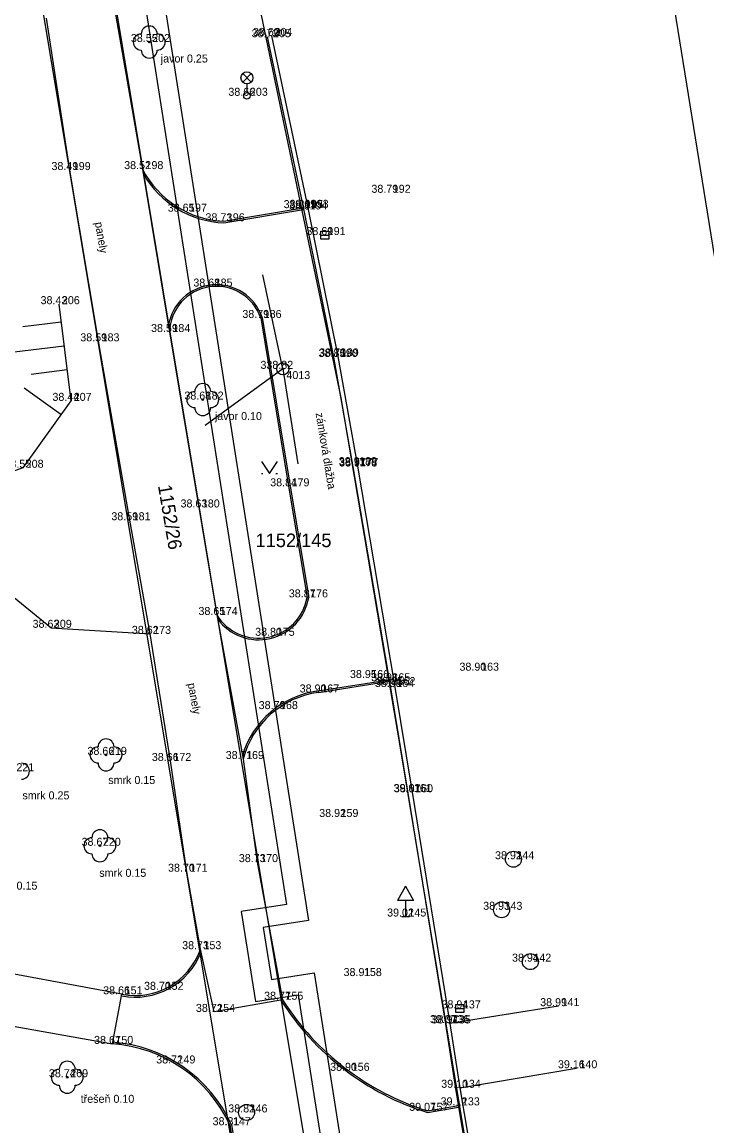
# Model space of a CAD drawing. Extents: x -609709 to -609357, y -1051535 to -1051131.
# Drawn here: x -609518.29 to -609496.91, y -1051297.25 to -1051262.77 of the extents above; entities that cross this region are included whole.
import ezdxf

# ---------------------------------------------------------------- set-up
doc = ezdxf.new("R2010")
doc.units = 0
for name, color, linetype in [('Vrstva 1', 7, 'Continuous'), ('Vrstva 10', 7, 'Continuous'), ('Vrstva 18', 7, 'Continuous'), ('Vrstva 19', 7, 'Continuous'), ('Vrstva 2', 7, 'Continuous'), ('Vrstva 3', 7, 'Continuous'), ('Vrstva 4', 7, 'Continuous'), ('Vrstva 5', 7, 'Continuous'), ('Vrstva 6', 7, 'Continuous'), ('Vrstva 7', 7, 'Continuous'), ('Vrstva 8', 7, 'Continuous')]:
    doc.layers.add(name, color=color, linetype=linetype)

msp = doc.modelspace()

# ---------------------------------------------------------------- linework, layer by layer
at = {"layer": 'Vrstva 1'}
for p, q in [((-609514.32, -1051263.39), (-609514.32, -1051263.39)), ((-609510.55, -1051263.24), (-609510.55, -1051263.24)), ((-609510.5, -1051263.2), (-609510.5, -1051263.2)), ((-609511.27, -1051265.07), (-609511.27, -1051265.07)), ((-609516.8, -1051267.39), (-609516.8, -1051267.39)), ((-609514.53, -1051267.36), (-609514.53, -1051267.36)), ((-609506.81, -1051268.1), (-609506.81, -1051268.1)), ((-609509.54, -1051268.58), (-609509.54, -1051268.58)), ((-609509.41, -1051268.62), (-609509.41, -1051268.62)), ((-609509.37, -1051268.57), (-609509.37, -1051268.57)), ((-609513.17, -1051268.69), (-609513.17, -1051268.69)), ((-609511.99, -1051268.99), (-609511.99, -1051268.99)), ((-609508.84, -1051269.42), (-609508.84, -1051269.42)), ((-609512.37, -1051271.03), (-609512.37, -1051271.03)), ((-609517.14, -1051271.58), (-609517.14, -1051271.58)), ((-609510.84, -1051272.01), (-609510.84, -1051272.01)), ((-609513.69, -1051272.45), (-609513.69, -1051272.45)), ((-609515.9, -1051272.74), (-609515.9, -1051272.74)), ((-609508.46, -1051273.23), (-609508.46, -1051273.23)), ((-609508.43, -1051273.21), (-609508.43, -1051273.21)), ((-609510.15, -1051273.6), (-609510.15, -1051273.6)), ((-609516.77, -1051274.6), (-609516.77, -1051274.6)), ((-609512.65, -1051274.56), (-609512.65, -1051274.56)), ((-609518.27, -1051276.69), (-609518.27, -1051276.69)), ((-609507.86, -1051276.61), (-609507.86, -1051276.61)), ((-609507.85, -1051276.65), (-609507.85, -1051276.65)), ((-609507.82, -1051276.64), (-609507.82, -1051276.64)), ((-609509.97, -1051277.27), (-609509.97, -1051277.27)), ((-609512.77, -1051277.93), (-609512.77, -1051277.93)), ((-609514.93, -1051278.33), (-609514.93, -1051278.33)), ((-609509.39, -1051280.74), (-609509.39, -1051280.74)), ((-609512.21, -1051281.29), (-609512.21, -1051281.29)), ((-609517.39, -1051281.69), (-609517.39, -1051281.69)), ((-609514.29, -1051281.88), (-609514.29, -1051281.88)), ((-609510.43, -1051281.94), (-609510.43, -1051281.94)), ((-609504.05, -1051283.03), (-609504.05, -1051283.03)), ((-609507.48, -1051283.26), (-609507.48, -1051283.26)), ((-609506.82, -1051283.36), (-609506.82, -1051283.36)), ((-609506.66, -1051283.48), (-609506.66, -1051283.48)), ((-609509.04, -1051283.71), (-609509.04, -1051283.71)), ((-609506.7, -1051283.54), (-609506.7, -1051283.54)), ((-609510.33, -1051284.23), (-609510.33, -1051284.23)), ((-609515.67, -1051285.66), (-609515.67, -1051285.66)), ((-609513.66, -1051285.85), (-609513.66, -1051285.85)), ((-609511.39, -1051285.79), (-609511.39, -1051285.79)), ((-609506.15, -1051286.82), (-609506.15, -1051286.82)), ((-609506.11, -1051286.83), (-609506.11, -1051286.83)), ((-609508.44, -1051287.6), (-609508.44, -1051287.6)), ((-609515.86, -1051288.5), (-609515.86, -1051288.5)), ((-609510.95, -1051289.01), (-609510.95, -1051289.01)), ((-609502.95, -1051288.92), (-609502.95, -1051288.92)), ((-609513.15, -1051289.31), (-609513.15, -1051289.31)), ((-609506.32, -1051290.71), (-609506.32, -1051290.71)), ((-609503.32, -1051290.5), (-609503.32, -1051290.5)), ((-609512.72, -1051291.73), (-609512.72, -1051291.73)), ((-609502.42, -1051292.12), (-609502.42, -1051292.12)), ((-609507.71, -1051292.57), (-609507.71, -1051292.57)), ((-609515.18, -1051293.14), (-609515.18, -1051293.14)), ((-609513.9, -1051293), (-609513.9, -1051293)), ((-609510.16, -1051293.31), (-609510.16, -1051293.31)), ((-609512.29, -1051293.69), (-609512.29, -1051293.69)), ((-609504.62, -1051293.58), (-609504.62, -1051293.58)), ((-609501.54, -1051293.51), (-609501.54, -1051293.51)), ((-609504.98, -1051294.04), (-609504.98, -1051294.04)), ((-609504.93, -1051294.05), (-609504.93, -1051294.05)), ((-609515.47, -1051294.69), (-609515.47, -1051294.69)), ((-609513.53, -1051295.3), (-609513.53, -1051295.3)), ((-609508.09, -1051295.53), (-609508.09, -1051295.53)), ((-609500.98, -1051295.45), (-609500.98, -1051295.45)), ((-609516.88, -1051295.73), (-609516.88, -1051295.73)), ((-609504.62, -1051296.06), (-609504.62, -1051296.06)), ((-609511.28, -1051296.83), (-609511.28, -1051296.83)), ((-609505.63, -1051296.78), (-609505.63, -1051296.78)), ((-609504.65, -1051296.61), (-609504.65, -1051296.61)), ((-609511.8, -1051297.23), (-609511.8, -1051297.23))]:
    msp.add_line(p, q, dxfattribs=at)
at = {"layer": 'Vrstva 10'}
for p, q in [((-609517.43, -1051249.92), (-609506.51, -1051315.51)), ((-609519.54, -1051251.09), (-609508.96, -1051314.48)), ((-609511.43, -1051259.63), (-609508.34, -1051274.51)), ((-609498.31, -1051259.99), (-609492.16, -1051298.11)), ((-609508.34, -1051274.51), (-609506.48, -1051285.5)), ((-609510.82, -1051276.495), (-609510.57, -1051276.87)), ((-609510.57, -1051276.87), (-609510.32, -1051276.495)), ((-609510.82, -1051276.87), (-609510.77, -1051276.87)), ((-609510.37, -1051276.87), (-609510.32, -1051276.87)), ((-609506.48, -1051285.5), (-609502.54, -1051309.21))]:
    msp.add_line(p, q, dxfattribs=at)
at = {"layer": 'Vrstva 18'}
for points in [[(-609510.15, -1051273.6), (-609510.778, -1051270.666)], [(-609510.15, -1051273.6), (-609512.571, -1051275.372)], [(-609510.15, -1051273.6), (-609509.678, -1051276.563)]]:
    msp.add_lwpolyline(points, dxfattribs=at)
for radius in [0.188, 0.025]:
    msp.add_circle((-609510.15, -1051273.6), radius, dxfattribs=at)
at = {"layer": 'Vrstva 19'}
for points in [[(-609514.503, -1051261.893), (-609510.036, -1051290.33), (-609511.446, -1051290.552), (-609511.003, -1051293.366), (-609509.669, -1051293.157), (-609503.864, -1051330.113)], [(-609513.91, -1051261.8), (-609509.35, -1051290.83), (-609510.76, -1051291.051), (-609510.504, -1051292.681), (-609509.17, -1051292.471), (-609503.272, -1051330.02)]]:
    msp.add_lwpolyline(points, dxfattribs=at)
at = {"layer": 'Vrstva 4'}
for p, q in [((-609511.987, -1051269.04), (-609509.502, -1051268.624)), ((-609510.791, -1051271.998), (-609509.921, -1051277.262)), ((-609509.921, -1051277.262), (-609509.339, -1051280.74)), ((-609509.047, -1051283.661), (-609506.831, -1051283.311)), ((-609505.633, -1051296.831), (-609504.661, -1051296.663))]:
    msp.add_line(p, q, dxfattribs=at)
for points in [[(-609515.4, -1051262.34), (-609514.53, -1051267.36), (-609513.69, -1051272.45), (-609512.77, -1051277.93), (-609512.21, -1051281.29), (-609511.39, -1051285.79), (-609510.95, -1051289.01), (-609510.16, -1051293.31), (-609512.29, -1051293.69), (-609512.72, -1051291.73)], [(-609512.72, -1051291.73), (-609513.15, -1051289.31), (-609513.66, -1051285.85), (-609514.29, -1051281.88), (-609514.93, -1051278.33), (-609515.9, -1051272.74), (-609516.8, -1051267.39), (-609517.53, -1051262.64)], [(-609510.637, -1051263.229), (-609509.507, -1051268.598), (-609508.568, -1051273.236), (-609507.958, -1051276.664), (-609506.798, -1051283.503), (-609506.248, -1051286.853), (-609505.068, -1051294.072), (-609504.758, -1051296.082), (-609504.098, -1051300.034), (-609503.728, -1051302.044), (-609503.168, -1051305.323), (-609502.501, -1051309.562)], [(-609510.5, -1051263.2), (-609509.37, -1051268.57), (-609508.43, -1051273.21), (-609507.82, -1051276.64), (-609506.66, -1051283.48), (-609506.11, -1051286.83), (-609504.93, -1051294.05), (-609504.62, -1051296.06), (-609503.96, -1051300.01), (-609503.59, -1051302.02), (-609503.03, -1051305.3), (-609502.36, -1051309.56)], [(-609511.99, -1051268.99), (-609509.512, -1051268.575)], [(-609510.84, -1051272.01), (-609509.97, -1051277.27), (-609509.39, -1051280.74)], [(-609517.39, -1051281.69), (-609519.87, -1051279.67), (-609524.23, -1051280.8), (-609526, -1051281.87)], [(-609517.39, -1051281.69), (-609514.29, -1051281.88)], [(-609509.04, -1051283.71), (-609506.822, -1051283.36)], [(-609515.47, -1051294.69), (-609515.18, -1051293.14), (-609520.01, -1051292.24), (-609525.19, -1051291.37), (-609531.18, -1051290.39), (-609535.64, -1051290.75), (-609539.66, -1051291.12)], [(-609542.53, -1051294.7), (-609539.02, -1051292.72), (-609535.48, -1051292.43), (-609531.05, -1051292.05), (-609525.42, -1051293.02), (-609520.39, -1051293.81), (-609515.47, -1051294.69)], [(-609501.54, -1051293.51), (-609504.93, -1051294.05)], [(-609504.62, -1051296.06), (-609500.98, -1051295.45)], [(-609505.63, -1051296.78), (-609504.669, -1051296.613)], [(-609511.8, -1051297.23), (-609510.59, -1051304.41), (-609509.94, -1051308.35), (-609509.47, -1051311.16), (-609511.1, -1051315.86)], [(-609511.752, -1051297.215), (-609510.541, -1051304.402), (-609509.891, -1051308.342), (-609509.419, -1051311.164), (-609511.053, -1051315.876)]]:
    msp.add_lwpolyline(points, dxfattribs=at)
for centre, radius, start, end in [((-609511.854, -1051265.984), 3.009, 207.2139, 267.4069), ((-609511.854, -1051265.984), 3.059, 209.9249, 267.5065), ((-609512.225, -1051272.488), 1.515, 18.8847, 171.1163), ((-609512.225, -1051272.488), 1.465, 19.0457, 178.507), ((-609510.905, -1051280.478), 1.537, 211.8899, 350.1824), ((-609510.905, -1051280.478), 1.587, 216.0744, 350.4918), ((-609508.664, -1051286.502), 2.867, 97.6736, 163.2956), ((-609508.664, -1051286.502), 2.817, 97.6623, 165.3622), ((-609514.765, -1051291.013), 2.167, 258.9582, 340.682), ((-609514.765, -1051291.013), 2.217, 258.9682, 338.6471), ((-609503.145, -1051288.844), 8.366, 212.3408, 252.6968), ((-609503.145, -1051288.844), 8.316, 212.4817, 252.6138), ((-609515.776, -1051299.054), 4.375, 24.64, 85.9859), ((-609515.776, -1051299.054), 4.425, 24.5541, 85.9112)]:
    msp.add_arc(centre, radius, start, end, dxfattribs=at)
at = {"layer": 'Vrstva 5'}
for p, q in [((-609511.402, -1051264.64), (-609511.138, -1051264.375)), ((-609511.402, -1051264.375), (-609511.138, -1051264.64)), ((-609511.27, -1051264.695), (-609511.27, -1051264.97)), ((-609508.965, -1051269.42), (-609508.715, -1051269.42)), ((-609506.32, -1051289.76), (-609506.57, -1051290.21)), ((-609506.32, -1051289.76), (-609506.07, -1051290.21)), ((-609506.07, -1051290.21), (-609506.57, -1051290.21)), ((-609506.32, -1051290.21), (-609506.32, -1051290.71)), ((-609506.445, -1051290.71), (-609506.195, -1051290.71)), ((-609504.745, -1051293.58), (-609504.495, -1051293.58))]:
    msp.add_line(p, q, dxfattribs=at)
for points in [[(-609508.965, -1051269.295), (-609508.715, -1051269.295), (-609508.715, -1051269.545), (-609508.965, -1051269.545)], [(-609504.745, -1051293.455), (-609504.495, -1051293.455), (-609504.495, -1051293.705), (-609504.745, -1051293.705)]]:
    msp.add_lwpolyline(points, close=True, dxfattribs=at)
for centre, radius in [((-609511.27, -1051264.508), 0.188), ((-609511.27, -1051265.07), 0.1), ((-609502.95, -1051288.92), 0.25), ((-609503.32, -1051290.5), 0.25), ((-609502.42, -1051292.12), 0.25), ((-609511.28, -1051296.83), 0.25)]:
    msp.add_circle(centre, radius, dxfattribs=at)
at = {"layer": 'Vrstva 6'}
msp.add_lwpolyline([(-609517.14, -1051271.58), (-609516.77, -1051274.6), (-609518.27, -1051276.69), (-609520.61, -1051277.55), (-609524.65, -1051280.21)], dxfattribs=at)
at = {"layer": 'Vrstva 7'}
for centre in [(-609514.32, -1051263.39), (-609512.65, -1051274.56), (-609515.67, -1051285.66), (-609515.86, -1051288.5), (-609516.88, -1051295.73)]:
    msp.add_circle(centre, 0.025, dxfattribs=at)
for centre, start, end in [((-609514.57, -1051263.39), 90, 270), ((-609514.32, -1051263.14), 0, 180), ((-609514.07, -1051263.39), 270, 90), ((-609514.32, -1051263.64), 180, 0), ((-609512.65, -1051274.31), 0, 180), ((-609512.9, -1051274.56), 90, 270), ((-609512.4, -1051274.56), 270, 90), ((-609512.65, -1051274.81), 180, 0), ((-609515.67, -1051285.41), 0, 180), ((-609515.92, -1051285.66), 90, 270), ((-609515.42, -1051285.66), 270, 90), ((-609515.67, -1051285.91), 180, 0), ((-609518.31, -1051286.17), 270, 90), ((-609516.11, -1051288.5), 90, 270), ((-609515.86, -1051288.25), 0, 180), ((-609515.61, -1051288.5), 270, 90), ((-609515.86, -1051288.75), 180, 0), ((-609517.13, -1051295.73), 90, 270), ((-609516.88, -1051295.48), 0, 180), ((-609516.63, -1051295.73), 270, 90), ((-609516.88, -1051295.98), 180, 0)]:
    msp.add_arc(centre, 0.25, start, end, dxfattribs=at)
at = {"layer": 'Vrstva 8'}
for p, q in [((-609517.071, -1051272.146), (-609518.268, -1051272.292)), ((-609516.979, -1051272.89), (-609519.881, -1051273.246)), ((-609516.888, -1051273.635), (-609518.012, -1051273.772)), ((-609517.078, -1051275.028), (-609518.227, -1051274.203))]:
    msp.add_line(p, q, dxfattribs=at)

# ---------------------------------------------------------------- texts
at = {"layer": 'Vrstva 10'}
msp.add_text('1152/26', height=0.425, rotation=279.6041, dxfattribs=at).set_placement((-609514.05, -1051277.25))
msp.add_text('1152/145', height=0.425, dxfattribs=at).set_placement((-609511, -1051279.17))
at = {"layer": 'Vrstva 18'}
msp.add_text(' 4013', height=0.25, dxfattribs=at).set_placement((-609510.13, -1051273.92))
at = {"layer": 'Vrstva 2'}
for s, p in [(' 202', (-609514.32, -1051263.39)), (' 205', (-609510.55, -1051263.24)), (' 204', (-609510.5, -1051263.2)), (' 203', (-609511.27, -1051265.07)), (' 199', (-609516.8, -1051267.39)), (' 198', (-609514.53, -1051267.36)), (' 192', (-609506.81, -1051268.1)), (' 195', (-609509.54, -1051268.58)), (' 193', (-609509.37, -1051268.57)), (' 197', (-609513.17, -1051268.69)), (' 194', (-609509.41, -1051268.62)), (' 196', (-609511.99, -1051268.99)), (' 191', (-609508.84, -1051269.42)), (' 185', (-609512.37, -1051271.03)), (' 206', (-609517.14, -1051271.58)), (' 186', (-609510.84, -1051272.01)), (' 184', (-609513.69, -1051272.45)), (' 183', (-609515.9, -1051272.74)), (' 190', (-609508.46, -1051273.23)), (' 189', (-609508.43, -1051273.21)), (' 207', (-609516.77, -1051274.6)), (' 182', (-609512.65, -1051274.56)), (' 208', (-609518.27, -1051276.69)), (' 188', (-609507.86, -1051276.61)), (' 178', (-609507.85, -1051276.65)), (' 177', (-609507.82, -1051276.64)), (' 179', (-609509.97, -1051277.27)), (' 180', (-609512.77, -1051277.93)), (' 181', (-609514.93, -1051278.33)), (' 176', (-609509.39, -1051280.74)), (' 174', (-609512.21, -1051281.29)), (' 209', (-609517.39, -1051281.69)), (' 173', (-609514.29, -1051281.88)), (' 175', (-609510.43, -1051281.94)), (' 163', (-609504.05, -1051283.03)), (' 166', (-609507.48, -1051283.26)), (' 165', (-609506.82, -1051283.36)), (' 167', (-609509.04, -1051283.71)), (' 164', (-609506.7, -1051283.54)), (' 162', (-609506.66, -1051283.48)), (' 168', (-609510.33, -1051284.23)), (' 219', (-609515.67, -1051285.66)), (' 169', (-609511.39, -1051285.79)), (' 172', (-609513.66, -1051285.85)), (' 221', (-609518.56, -1051286.17)), (' 161', (-609506.15, -1051286.82)), (' 160', (-609506.11, -1051286.83)), (' 159', (-609508.44, -1051287.6)), (' 220', (-609515.86, -1051288.5)), (' 144', (-609502.95, -1051288.92)), (' 170', (-609510.95, -1051289.01)), (' 171', (-609513.15, -1051289.31)), (' 143', (-609503.32, -1051290.5)), (' 145', (-609506.32, -1051290.71)), (' 153', (-609512.72, -1051291.73)), (' 142', (-609502.42, -1051292.12)), (' 158', (-609507.71, -1051292.57)), (' 152', (-609513.9, -1051293)), (' 151', (-609515.18, -1051293.14)), (' 155', (-609510.16, -1051293.31)), (' 154', (-609512.29, -1051293.69)), (' 137', (-609504.62, -1051293.58)), (' 141', (-609501.54, -1051293.51)), (' 136', (-609504.98, -1051294.04)), (' 135', (-609504.93, -1051294.05)), (' 150', (-609515.47, -1051294.69)), (' 149', (-609513.53, -1051295.3)), (' 140', (-609500.98, -1051295.45)), (' 269', (-609516.88, -1051295.73)), (' 156', (-609508.09, -1051295.53)), (' 134', (-609504.62, -1051296.06)), (' 146', (-609511.28, -1051296.83)), (' 157', (-609505.63, -1051296.78)), (' 133', (-609504.65, -1051296.61)), (' 147', (-609511.8, -1051297.23))]:
    msp.add_text(s, height=0.25, dxfattribs=at).set_placement(p)
at = {"layer": 'Vrstva 3'}
for s, p in [('38.55', (-609514.893, -1051263.39)), ('38.73', (-609511.123, -1051263.24)), ('38.60', (-609511.083, -1051263.2)), ('38.66', (-609511.849, -1051265.07)), ('38.49', (-609517.373, -1051267.39)), ('38.52', (-609515.103, -1051267.36)), ('38.79', (-609507.383, -1051268.1)), ('38.80', (-609510.123, -1051268.58)), ('38.69', (-609509.943, -1051268.57)), ('38.65', (-609513.743, -1051268.69)), ('38.81', (-609509.952, -1051268.62)), ('38.73', (-609512.563, -1051268.99)), ('38.69', (-609509.413, -1051269.42)), ('38.68', (-609512.943, -1051271.03)), ('38.43', (-609517.713, -1051271.58)), ('38.79', (-609511.413, -1051272.01)), ('38.59', (-609514.263, -1051272.45)), ('38.59', (-609516.473, -1051272.74)), ('38.85', (-609509.033, -1051273.23)), ('38.70', (-609509.013, -1051273.21)), ('338.82', (-609510.848, -1051273.6)), ('38.44', (-609517.343, -1051274.6)), ('38.68', (-609513.223, -1051274.56)), ('38.55', (-609518.843, -1051276.69)), ('38.91', (-609508.402, -1051276.61)), ('38.77', (-609508.393, -1051276.64)), ('38.91', (-609508.392, -1051276.65)), ('38.84', (-609510.543, -1051277.27)), ('38.63', (-609513.343, -1051277.93)), ('38.59', (-609515.503, -1051278.33)), ('38.87', (-609509.963, -1051280.74)), ('38.65', (-609512.783, -1051281.29)), ('38.63', (-609517.963, -1051281.69)), ('38.62', (-609514.863, -1051281.88)), ('38.80', (-609511.013, -1051281.94)), ('38.90', (-609504.633, -1051283.03)), ('38.95', (-609508.053, -1051283.26)), ('38.98', (-609507.393, -1051283.36)), ('38.90', (-609509.623, -1051283.71)), ('38.98', (-609507.273, -1051283.54)), ('38.85', (-609507.233, -1051283.48)), ('38.79', (-609510.903, -1051284.23)), ('38.66', (-609516.249, -1051285.66)), ('38.71', (-609511.932, -1051285.79)), ('38.66', (-609514.239, -1051285.85)), ('39.01', (-609506.692, -1051286.82)), ('38.87', (-609506.683, -1051286.83)), ('38.92', (-609509.013, -1051287.6)), ('38.67', (-609516.433, -1051288.5)), ('38.92', (-609503.523, -1051288.92)), ('38.73', (-609511.523, -1051289.01)), ('38.70', (-609513.733, -1051289.31)), ('38.93', (-609503.893, -1051290.5)), ('39.02', (-609506.893, -1051290.71)), ('38.73', (-609513.293, -1051291.73)), ('38.94', (-609502.993, -1051292.12)), ('38.91', (-609508.252, -1051292.57)), ('38.70', (-609514.483, -1051293)), ('38.66', (-609515.759, -1051293.14)), ('38.77', (-609510.733, -1051293.31)), ('38.72', (-609512.863, -1051293.69)), ('38.94', (-609505.193, -1051293.58)), ('38.99', (-609502.113, -1051293.51)), ('39.07', (-609505.553, -1051294.04)), ('38.97', (-609505.503, -1051294.05)), ('38.67', (-609516.043, -1051294.69)), ('38.72', (-609514.103, -1051295.3)), ('39.16', (-609501.559, -1051295.45)), ('38.74', (-609517.453, -1051295.73)), ('38.90', (-609508.673, -1051295.53)), ('39.10', (-609505.203, -1051296.06)), ('38.82', (-609511.853, -1051296.83)), ('39.07', (-609506.203, -1051296.78)), ('39.12', (-609505.223, -1051296.61)), ('38.81', (-609512.342, -1051297.23))]:
    msp.add_text(s, height=0.25, dxfattribs=at).set_placement(p)
at = {"layer": 'Vrstva 4'}
for s, rotation, p in [('panely', 279.5491, (-609516.017, -1051269.032)), ('zámková dlažba', 279.3917, (-609509.126, -1051274.99)), ('panely', 280.2196, (-609513.119, -1051283.437))]:
    msp.add_text(s, height=0.25, rotation=rotation, dxfattribs=at).set_placement(p)
at = {"layer": 'Vrstva 7'}
for s, p in [('javor 0.25', (-609513.96, -1051264.03)), ('javor 0.10', (-609512.27, -1051275.2)), ('smrk 0.15', (-609515.6, -1051286.57)), ('smrk 0.25', (-609518.28, -1051287.05)), ('smrk 0.15', (-609515.88, -1051289.47)), ('smrk 0.15', (-609519.28, -1051289.87)), ('třešeň 0.10', (-609516.46, -1051296.53))]:
    msp.add_text(s, height=0.25, dxfattribs=at).set_placement(p)

doc.saveas('drawing.dxf')
